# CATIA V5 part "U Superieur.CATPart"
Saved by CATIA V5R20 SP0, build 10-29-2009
Part number: U Superieur
Bounding box of the stored display mesh (mm): x -31.5 to -16.5, y 41.5 to 45.5, z -19.5 to -2.5
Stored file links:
  E:\Boulot\SeaTech\2eme ANNEE\FabricationAdditive\TP_MOSM_CREM\Projet Sauterelle de serrage\CAO Assemblage Sauterelle\U Superieur.CATPart
  E:\Boulot\SeaTech\2eme ANNEE\FabricationAdditive\TP_MOSM_CREM\Projet Sauterelle de serrage\CAO Assemblage Sauterelle\Sauterelle_horizontale_05120-06.CATPart
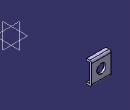
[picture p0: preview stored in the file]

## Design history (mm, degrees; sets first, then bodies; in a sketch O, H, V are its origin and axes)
Body1 (main body)
  Solid1 "05120-06_7": solid without history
